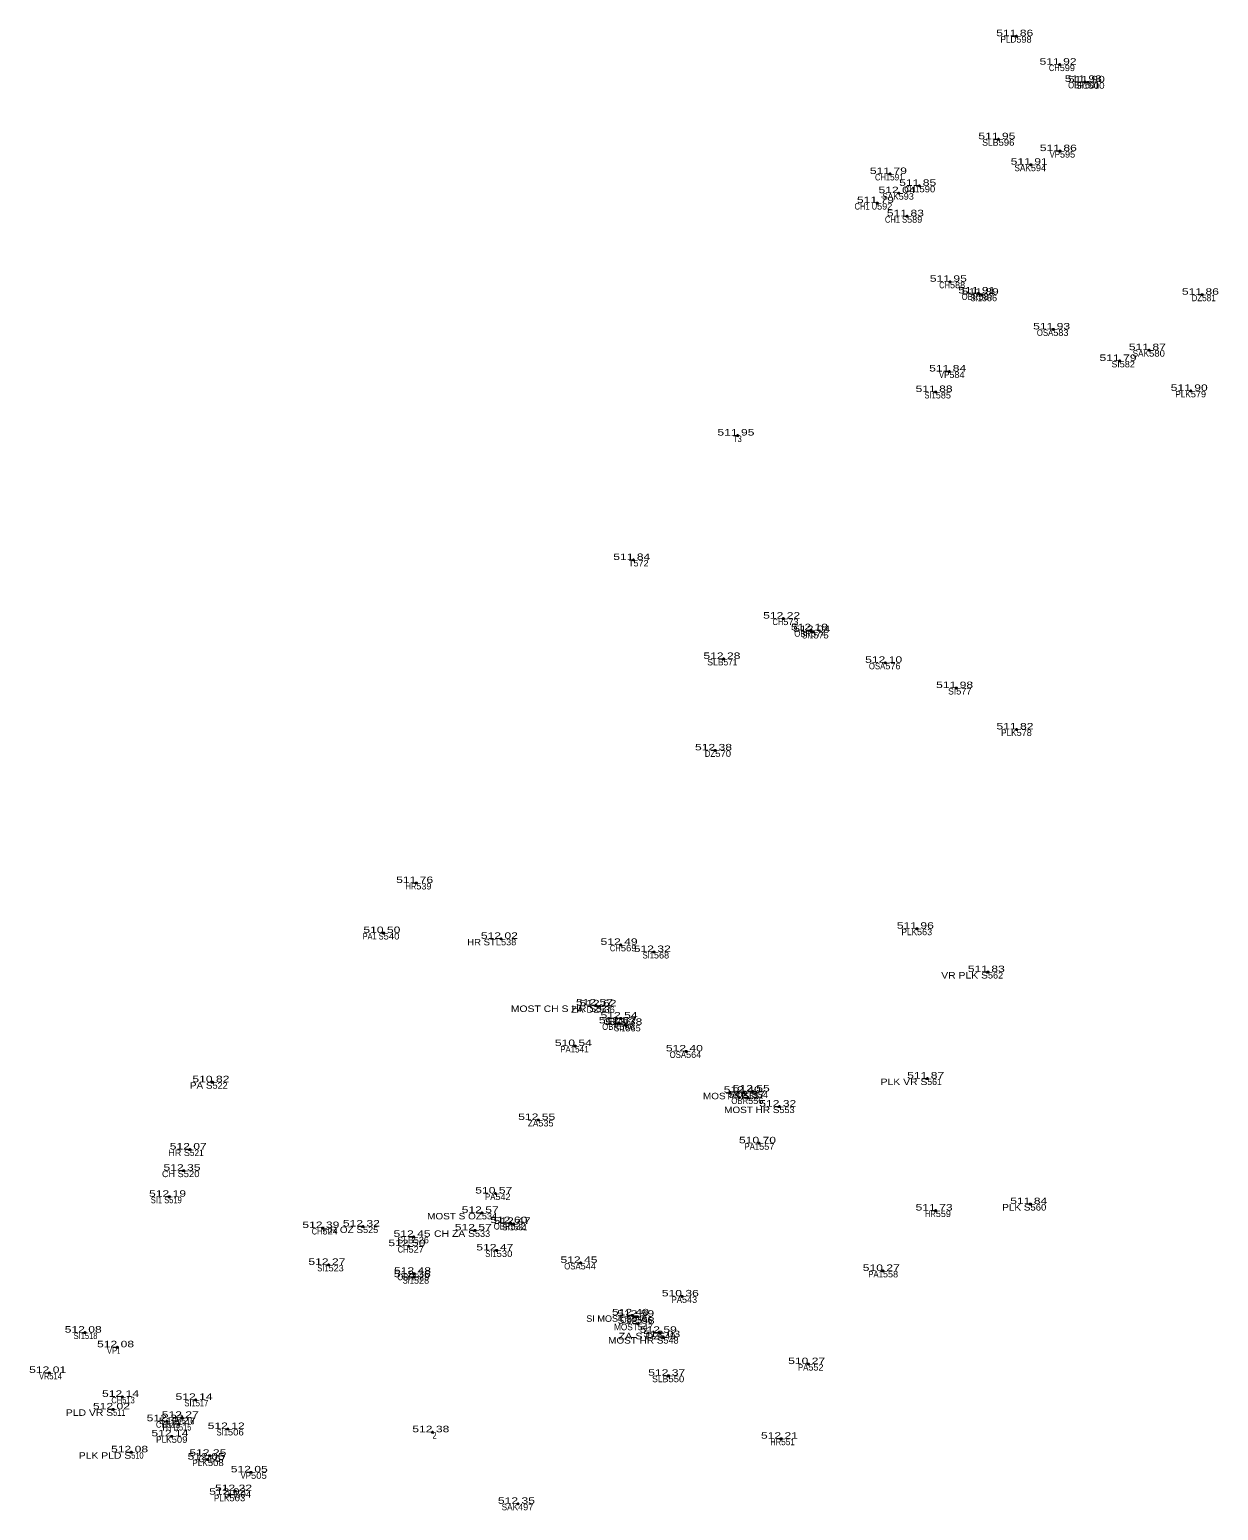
# Model space of a CAD drawing. Extents: x -643086 to -639283, y -1131805 to -1123269.
# Drawn here: x -639379 to -639323.9, y -1123407.7 to -1123339 of the extents above; entities that cross this region are included whole.
import ezdxf
from ezdxf.enums import TextEntityAlignment as Align

# ---------------------------------------------------------------- set-up
doc = ezdxf.new("R2010")
doc.units = 0
doc.header["$LTSCALE"] = 0.12
doc.header["$PDMODE"] = 32
doc.header["$PDSIZE"] = 0.06
for name, color, linetype in [('1', 7, 'Continuous'), ('2', 7, 'Continuous'), ('3', 7, 'Continuous'), ('4', 7, 'Continuous')]:
    doc.layers.add(name, color=color, linetype=linetype)

msp = doc.modelspace()

# ---------------------------------------------------------------- linework, layer by layer
at = {"layer": '1'}
for p in [(-639333.25, -1123339.34), (-639331.24, -1123340.66), (-639330.07, -1123341.46), (-639329.93, -1123341.48), (-639334.08, -1123344.12), (-639331.23, -1123344.67), (-639332.58, -1123345.3), (-639339.11, -1123345.73), (-639337.75, -1123346.28), (-639338.71, -1123346.62), (-639339.71, -1123347.08), (-639338.32, -1123347.69), (-639336.33, -1123350.73), (-639335.01, -1123351.27), (-639334.85, -1123351.33), (-639324.64, -1123351.33), (-639331.54, -1123352.94), (-639328.46, -1123354.4), (-639327.1, -1123353.9), (-639336.36, -1123354.89), (-639336.99, -1123355.84), (-639325.16, -1123355.79), (-639346.18, -1123357.86), (-639351.01, -1123363.63), (-639344.06, -1123366.35), (-639342.77, -1123366.89), (-639342.66, -1123366.97), (-639346.83, -1123368.22), (-639339.33, -1123368.4), (-639336.04, -1123369.57), (-639333.24, -1123371.49), (-639347.22, -1123372.46), (-639361.08, -1123378.61), (-639362.6, -1123380.93), (-639357.15, -1123381.2), (-639337.86, -1123380.73), (-639351.6, -1123381.48), (-639350.06, -1123381.81), (-639334.57, -1123382.74), (-639352.74, -1123384.29), (-639352.58, -1123384.33), (-639351.68, -1123385.12), (-639351.6, -1123384.89), (-639351.38, -1123385.19), (-639353.72, -1123386.17), (-639348.57, -1123386.42), (-639370.53, -1123387.85), (-639337.38, -1123387.68), (-639345.89, -1123388.34), (-639345.69, -1123388.56), (-639345.47, -1123388.28), (-639344.24, -1123388.98), (-639355.42, -1123389.6), (-639345.18, -1123390.68), (-639371.58, -1123390.97), (-639371.87, -1123391.95), (-639372.54, -1123393.16), (-639357.41, -1123393.01), (-639332.6, -1123393.5), (-639358.04, -1123393.91), (-639336.99, -1123393.8), (-639365.43, -1123394.61), (-639363.55, -1123394.54), (-639361.2, -1123395.02), (-639358.36, -1123394.72), (-639356.71, -1123394.38), (-639356.56, -1123394.42), (-639361.44, -1123395.45), (-639357.36, -1123395.65), (-639365.15, -1123396.32), (-639353.46, -1123396.23), (-639361.19, -1123396.89), (-639361.18, -1123396.73), (-639339.44, -1123396.6), (-639348.76, -1123397.78), (-639351.07, -1123398.66), (-639350.83, -1123398.72), (-639350.81, -1123399.05), (-639376.45, -1123399.46), (-639349.78, -1123399.47), (-639349.62, -1123399.67), (-639374.95, -1123400.14), (-639342.9, -1123400.92), (-639378.1, -1123401.33), (-639349.39, -1123401.46), (-639374.72, -1123402.44), (-639371.31, -1123402.58), (-639375.14, -1123403.02), (-639372.65, -1123403.57), (-639372.09, -1123403.7), (-639371.95, -1123403.41), (-639369.82, -1123403.93), (-639372.43, -1123404.27), (-639360.33, -1123404.08), (-639344.16, -1123404.38), (-639374.3, -1123405.01), (-639370.67, -1123405.17), (-639370.75, -1123405.35), (-639368.75, -1123405.94), (-639369.75, -1123406.98), (-639369.48, -1123406.81), (-639356.36, -1123407.4)]:
    msp.add_point(p, dxfattribs=at)

# ---------------------------------------------------------------- texts
at = {"layer": '2'}
for s, width, p in [('598', 1.05, (-639333.25, -1123339.64)), ('599', 1.05, (-639331.24, -1123340.96)), ('600', 1.15, (-639329.93, -1123341.78)), ('596', 1.1, (-639334.08, -1123344.42)), ('595', 1.05, (-639331.23, -1123344.97)), ('594', 1.05, (-639332.58, -1123345.6)), ('591', 0.95, (-639339.11, -1123346.03)), ('593', 1.05, (-639338.71, -1123346.92)), ('590', 1.1, (-639337.75, -1123346.58)), ('592', 1.05, (-639339.71, -1123347.38)), ('589', 1.05, (-639338.32, -1123347.99)), ('588', 1.05, (-639336.33, -1123351.03)), ('587', 1.05, (-639335.01, -1123351.57)), ('586', 1.05, (-639334.85, -1123351.63)), ('581', 0.95, (-639324.64, -1123351.63)), ('583', 1.05, (-639331.54, -1123353.24)), ('582', 1.05, (-639328.46, -1123354.7)), ('580', 1.1, (-639327.1, -1123354.2)), ('584', 1.05, (-639336.36, -1123355.19)), ('585', 1.05, (-639336.99, -1123356.14)), ('579', 1.05, (-639325.16, -1123356.09)), ('3', 0.75, (-639346.18, -1123358.16)), ('572', 1.05, (-639351.01, -1123363.93)), ('573', 1.05, (-639344.06, -1123366.65)), ('574', 1.05, (-639342.77, -1123367.19)), ('575', 1.05, (-639342.66, -1123367.27)), ('571', 0.95, (-639346.83, -1123368.52)), ('576', 1.05, (-639339.33, -1123368.7)), ('577', 1.05, (-639336.04, -1123369.87)), ('578', 1.05, (-639333.24, -1123371.79)), ('570', 1.1, (-639347.22, -1123372.76)), ('539', 1.05, (-639361.08, -1123378.91)), ('540', 1.1, (-639362.6, -1123381.23)), ('538', 1.05, (-639357.15, -1123381.5)), ('563', 1.05, (-639337.86, -1123381.03)), ('569', 1.1, (-639351.6, -1123381.78)), ('568', 1.05, (-639350.06, -1123382.11)), ('562', 1.05, (-639334.57, -1123383.04)), ('537', 1.05, (-639352.74, -1123384.59)), ('536', 1.05, (-639352.58, -1123384.63)), ('566', 1.1, (-639351.68, -1123385.42)), ('567', 1.05, (-639351.6, -1123385.19)), ('565', 1.05, (-639351.38, -1123385.49)), ('541', 0.95, (-639353.72, -1123386.47)), ('564', 1.05, (-639348.57, -1123386.72)), ('522', 1.05, (-639370.53, -1123388.15)), ('555', 1.05, (-639345.89, -1123388.64)), ('556', 1.05, (-639345.69, -1123388.86)), ('554', 1.05, (-639345.47, -1123388.58)), ('553', 1.05, (-639344.24, -1123389.28)), ('535', 1.05, (-639355.42, -1123389.9)), ('557', 1.05, (-639345.18, -1123390.98)), ('521', 0.95, (-639371.58, -1123391.27)), ('520', 1.1, (-639371.87, -1123392.25)), ('519', 0.8, (-639372.54, -1123393.46)), ('542', 1.05, (-639357.41, -1123393.31)), ('560', 1.1, (-639332.6, -1123393.8)), ('534', 1.05, (-639358.04, -1123394.21)), ('559', 1.05, (-639336.99, -1123394.1)), ('524', 1.05, (-639365.43, -1123394.91)), ('525', 1.05, (-639363.55, -1123394.84)), ('533', 1.05, (-639358.36, -1123395.02)), ('532', 1.05, (-639356.71, -1123394.68)), ('531', 0.95, (-639356.56, -1123394.72)), ('527', 1.05, (-639361.44, -1123395.75)), ('526', 1.05, (-639361.2, -1123395.32)), ('530', 1.1, (-639357.36, -1123395.95)), ('523', 1.05, (-639365.15, -1123396.62)), ('544', 1.05, (-639353.46, -1123396.53)), ('528', 1.05, (-639361.19, -1123397.19)), ('529', 1.05, (-639361.18, -1123397.03)), ('558', 1.05, (-639339.44, -1123396.9)), ('543', 1.05, (-639348.76, -1123398.08)), ('545', 1.05, (-639351.07, -1123398.96)), ('546', 1.05, (-639350.83, -1123399.02)), ('547', 1.05, (-639350.81, -1123399.35)), ('518', 0.8, (-639376.45, -1123399.76)), ('549', 1.05, (-639349.78, -1123399.77)), ('548', 1.05, (-639349.62, -1123399.97)), ('1', 0.45, (-639374.95, -1123400.44)), ('552', 1.05, (-639342.9, -1123401.22)), ('514', 0.8, (-639378.1, -1123401.63)), ('550', 1.1, (-639349.39, -1123401.76)), ('513', 0.8, (-639374.72, -1123402.74)), ('511', 0.7, (-639375.14, -1123403.32)), ('517', 0.8, (-639371.31, -1123402.88)), ('512', 0.8, (-639372.65, -1123403.87)), ('515', 0.8, (-639372.09, -1123404)), ('516', 0.8, (-639371.95, -1123403.71)), ('506', 1.1, (-639369.82, -1123404.23)), ('509', 1.1, (-639372.43, -1123404.57)), ('2', 0.75, (-639360.33, -1123404.38)), ('551', 0.95, (-639344.16, -1123404.68)), ('510', 0.85, (-639374.3, -1123405.31)), ('507', 1.1, (-639370.67, -1123405.47)), ('508', 1.1, (-639370.75, -1123405.65)), ('505', 1.1, (-639368.75, -1123406.24)), ('503', 1.1, (-639369.75, -1123407.28)), ('504', 1.1, (-639369.48, -1123407.11)), ('497', 1.05, (-639356.36, -1123407.7))]:
    msp.add_text(s, height=0.3, dxfattribs=dict(at, width=width)).set_placement(p)
for s, p in [('601', (-639330.07, -1123341.76)), ('561', (-639337.38, -1123387.98))]:
    msp.add_text(s, height=0.3, dxfattribs=at).set_placement(p)
at = {"layer": '3', "width": 1.4}
for s, p in [('511 86 ', (-639333.25, -1123339.34)), ('511 92 ', (-639331.24, -1123340.66)), ('511 93 ', (-639330.07, -1123341.46)), ('511 90 ', (-639329.93, -1123341.48)), ('511 95 ', (-639334.08, -1123344.12)), ('511 86 ', (-639331.23, -1123344.67)), ('511 79 ', (-639339.11, -1123345.73)), ('511 91 ', (-639332.58, -1123345.3)), ('511 85 ', (-639337.75, -1123346.28)), ('511 79 ', (-639339.71, -1123347.08)), ('512 04 ', (-639338.71, -1123346.62)), ('511 83 ', (-639338.32, -1123347.69)), ('511 95 ', (-639336.33, -1123350.73)), ('511 91 ', (-639335.01, -1123351.27)), ('511 89 ', (-639334.85, -1123351.33)), ('511 86 ', (-639324.64, -1123351.33)), ('511 93 ', (-639331.54, -1123352.94)), ('511 87 ', (-639327.1, -1123353.9)), ('511 79 ', (-639328.46, -1123354.4)), ('511 84 ', (-639336.36, -1123354.89)), ('511 88 ', (-639336.99, -1123355.84)), ('511 90 ', (-639325.16, -1123355.79)), ('511 95 ', (-639346.18, -1123357.86)), ('511 84 ', (-639351.01, -1123363.63)), ('512 22 ', (-639344.06, -1123366.35)), ('512 18 ', (-639342.77, -1123366.89)), ('512 04 ', (-639342.66, -1123366.97)), ('512 28 ', (-639346.83, -1123368.22)), ('512 10 ', (-639339.33, -1123368.4)), ('511 98 ', (-639336.04, -1123369.57)), ('511 82 ', (-639333.24, -1123371.49)), ('512 38 ', (-639347.22, -1123372.46)), ('511 76 ', (-639361.08, -1123378.61)), ('511 96 ', (-639337.86, -1123380.73)), ('510 50 ', (-639362.6, -1123380.93)), ('512 02 ', (-639357.15, -1123381.2)), ('512 49 ', (-639351.6, -1123381.48)), ('512 32 ', (-639350.06, -1123381.81)), ('511 83 ', (-639334.57, -1123382.74)), ('512 57 ', (-639352.74, -1123384.29)), ('512 62 ', (-639352.58, -1123384.33)), ('512 54 ', (-639351.6, -1123384.89)), ('512 57 ', (-639351.68, -1123385.12)), ('512 38 ', (-639351.38, -1123385.19)), ('510 54 ', (-639353.72, -1123386.17)), ('512 40 ', (-639348.57, -1123386.42)), ('511 87 ', (-639337.38, -1123387.68)), ('510 82 ', (-639370.53, -1123387.85)), ('512 40 ', (-639345.89, -1123388.34)), ('512 55 ', (-639345.47, -1123388.28)), ('512 57 ', (-639345.69, -1123388.56)), ('512 32 ', (-639344.24, -1123388.98)), ('512 55 ', (-639355.42, -1123389.6)), ('512 07 ', (-639371.58, -1123390.97)), ('510 70 ', (-639345.18, -1123390.68)), ('512 35 ', (-639371.87, -1123391.95)), ('512 19 ', (-639372.54, -1123393.16)), ('510 57 ', (-639357.41, -1123393.01)), ('512 57 ', (-639358.04, -1123393.91)), ('511 73 ', (-639336.99, -1123393.8)), ('511 84 ', (-639332.6, -1123393.5)), ('512 39 ', (-639365.43, -1123394.61)), ('512 32 ', (-639363.55, -1123394.54)), ('512 60 ', (-639356.71, -1123394.38)), ('512 47 ', (-639356.56, -1123394.42)), ('512 45 ', (-639361.2, -1123395.02)), ('512 57 ', (-639358.36, -1123394.72)), ('512 50 ', (-639361.44, -1123395.45)), ('512 47 ', (-639357.36, -1123395.65)), ('512 27 ', (-639365.15, -1123396.32)), ('512 45 ', (-639353.46, -1123396.23)), ('510 27 ', (-639339.44, -1123396.6)), ('512 36 ', (-639361.19, -1123396.89)), ('512 48 ', (-639361.18, -1123396.73)), ('510 36 ', (-639348.76, -1123397.78)), ('512 48 ', (-639351.07, -1123398.66)), ('512 59 ', (-639350.83, -1123398.72)), ('512 58 ', (-639350.81, -1123399.05)), ('512 08 ', (-639376.45, -1123399.46)), ('512 59 ', (-639349.78, -1123399.47)), ('512 03 ', (-639349.62, -1123399.67)), ('512 08 ', (-639374.95, -1123400.14)), ('512 01 ', (-639378.1, -1123401.33)), ('512 37 ', (-639349.39, -1123401.46)), ('510 27 ', (-639342.9, -1123400.92)), ('512 14 ', (-639374.72, -1123402.44)), ('512 14 ', (-639371.31, -1123402.58)), ('512 02 ', (-639375.14, -1123403.02)), ('512 27 ', (-639371.95, -1123403.41)), ('512 32 ', (-639372.65, -1123403.57)), ('512 27 ', (-639372.09, -1123403.7)), ('512 12 ', (-639369.82, -1123403.93)), ('512 38 ', (-639360.33, -1123404.08)), ('512 14 ', (-639372.43, -1123404.27)), ('512 21 ', (-639344.16, -1123404.38)), ('512 08 ', (-639374.3, -1123405.01)), ('512 05 ', (-639370.75, -1123405.35)), ('512 25 ', (-639370.67, -1123405.17)), ('512 05 ', (-639368.75, -1123405.94)), ('512 02 ', (-639369.75, -1123406.98)), ('512 22 ', (-639369.48, -1123406.81)), ('512 35 ', (-639356.36, -1123407.4))]:
    msp.add_text(s, height=0.3, dxfattribs=at).set_placement(p, align=Align.CENTER)
at = {"layer": '4'}
for s, width, p in [('PLD', 0.95, (-639333.25, -1123339.64)), ('CH', 0.8, (-639331.24, -1123340.96)), ('OBR', 0.9, (-639330.07, -1123341.76)), ('SI1', 0.8, (-639329.93, -1123341.78)), ('VP', 0.9, (-639331.23, -1123344.97)), ('SAK', 0.95, (-639332.58, -1123345.6)), ('CH1', 0.8, (-639339.11, -1123346.03)), ('SAK', 0.95, (-639338.71, -1123346.92)), ('CH1', 0.8, (-639337.75, -1123346.58)), ('CH1 U', 0.8, (-639339.71, -1123347.38)), ('CH1 S', 0.8, (-639338.32, -1123347.99)), ('CH', 0.8, (-639336.33, -1123351.03)), ('OBR', 0.9, (-639335.01, -1123351.57)), ('SI1', 0.8, (-639334.85, -1123351.63)), ('DZ', 0.9, (-639324.64, -1123351.63)), ('OSA', 0.9, (-639331.54, -1123353.24)), ('SAK', 0.95, (-639327.1, -1123354.2)), ('VP', 0.9, (-639336.36, -1123355.19)), ('SI1', 0.8, (-639336.99, -1123356.14)), ('PLK', 0.95, (-639325.16, -1123356.09)), ('T', 0.8, (-639346.18, -1123358.16)), ('T', 0.8, (-639351.01, -1123363.93)), ('CH', 0.8, (-639344.06, -1123366.65)), ('OBR', 0.9, (-639342.77, -1123367.19)), ('SI1', 0.8, (-639342.66, -1123367.27)), ('OSA', 0.9, (-639339.33, -1123368.7)), ('PLK', 0.95, (-639333.24, -1123371.79)), ('DZ', 0.9, (-639347.22, -1123372.76)), ('HR', 0.8, (-639361.08, -1123378.91)), ('PA1 S', 0.85, (-639362.6, -1123381.23)), ('HR STL', 1.1, (-639357.15, -1123381.5)), ('PLK', 0.95, (-639337.86, -1123381.03)), ('CH', 0.8, (-639351.6, -1123381.78)), ('SI1', 0.8, (-639350.06, -1123382.11)), ('VR PLK S', 1.2, (-639334.57, -1123383.04)), ('MOST CH S HR S', 1.2, (-639352.74, -1123384.59)), ('ZA DZ', 1.15, (-639352.58, -1123384.63)), ('OBR', 0.9, (-639351.68, -1123385.42)), ('OBR', 0.9, (-639351.6, -1123385.19)), ('SI1', 0.8, (-639351.38, -1123385.49)), ('PA1', 0.9, (-639353.72, -1123386.47)), ('OSA', 0.9, (-639348.57, -1123386.72)), ('PA S', 1.15, (-639370.53, -1123388.15)), ('PLK VR S', 1.2, (-639337.38, -1123387.98)), ('MOST SI', 1.15, (-639345.89, -1123388.64)), ('MOST', 0.95, (-639345.47, -1123388.58)), ('OBR', 0.9, (-639345.69, -1123388.86)), ('MOST HR S', 1.15, (-639344.24, -1123389.28)), ('ZA', 0.95, (-639355.42, -1123389.9)), ('PA1', 0.9, (-639345.18, -1123390.98)), ('HR S', 1.05, (-639371.58, -1123391.27)), ('CH S', 1.05, (-639371.87, -1123392.25)), ('SI1 S', 0.8, (-639372.54, -1123393.46)), ('PA', 0.9, (-639357.41, -1123393.31)), ('PLK S', 1.15, (-639332.6, -1123393.8)), ('MOST S OZ', 1.15, (-639358.04, -1123394.21)), ('HR', 0.8, (-639336.99, -1123394.1)), ('CH', 0.8, (-639365.43, -1123394.91)), ('HR OZ S', 1.15, (-639363.55, -1123394.84)), ('CH ZA S', 1.2, (-639358.36, -1123395.02)), ('OBR', 0.9, (-639356.71, -1123394.68)), ('SI1', 0.8, (-639356.56, -1123394.72)), ('CH', 0.8, (-639361.44, -1123395.75)), ('SI1', 0.8, (-639357.36, -1123395.95)), ('SI1', 0.8, (-639365.15, -1123396.62)), ('OSA', 0.9, (-639353.46, -1123396.53)), ('OBR', 0.9, (-639361.18, -1123397.03)), ('SI1', 0.8, (-639361.19, -1123397.19)), ('PA1', 0.9, (-639339.44, -1123396.9)), ('PA', 0.9, (-639348.76, -1123398.08)), ('SI MOST S', 1.05, (-639351.07, -1123398.96)), ('MOST', 0.95, (-639350.81, -1123399.35)), ('OBR', 0.9, (-639350.83, -1123399.02)), ('SI1', 0.8, (-639376.45, -1123399.76)), ('MOST HR S', 1.15, (-639349.62, -1123399.97)), ('ZA S DZ', 1.25, (-639349.78, -1123399.77)), ('VP', 0.9, (-639374.95, -1123400.44)), ('PA', 0.9, (-639342.9, -1123401.22)), ('VR', 0.85, (-639378.1, -1123401.63)), ('CH', 0.8, (-639374.72, -1123402.74)), ('PLD VR S', 1.2, (-639375.14, -1123403.32)), ('SI1', 0.8, (-639371.31, -1123402.88)), ('CH', 0.8, (-639372.65, -1123403.87)), ('HYD', 0.9, (-639372.09, -1123404)), ('SV', 0.9, (-639371.95, -1123403.71)), ('SI1', 0.8, (-639369.82, -1123404.23)), ('PLK', 0.95, (-639372.43, -1123404.57)), ('HR', 0.8, (-639344.16, -1123404.68)), ('PLK PLD S', 1.2, (-639374.3, -1123405.31)), ('CH', 0.8, (-639370.67, -1123405.47)), ('PLK', 0.95, (-639370.75, -1123405.65)), ('VP', 0.9, (-639368.75, -1123406.24)), ('PLK', 0.95, (-639369.75, -1123407.28)), ('CH', 0.8, (-639369.48, -1123407.11)), ('SAK', 0.95, (-639356.36, -1123407.7))]:
    msp.add_text(s, height=0.3, dxfattribs=dict(at, width=width)).set_placement(p, align=Align.RIGHT)
for s, p in [('SLB', (-639334.08, -1123344.42)), ('SI', (-639328.46, -1123354.7)), ('SLB', (-639346.83, -1123368.52)), ('SI', (-639336.04, -1123369.87)), ('SLB', (-639361.2, -1123395.32)), ('SLB', (-639349.39, -1123401.76))]:
    msp.add_text(s, height=0.3, dxfattribs=at).set_placement(p, align=Align.RIGHT)

doc.saveas('drawing.dxf')
